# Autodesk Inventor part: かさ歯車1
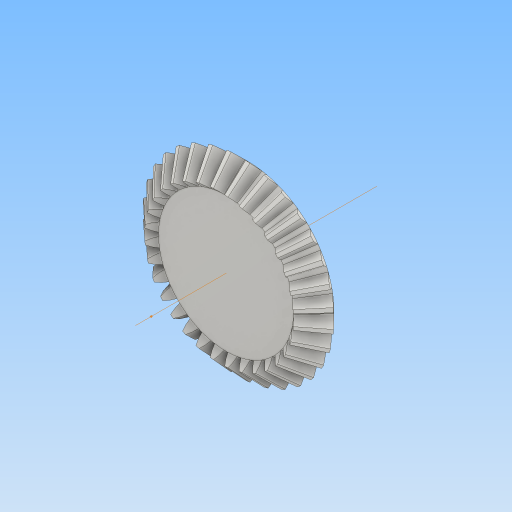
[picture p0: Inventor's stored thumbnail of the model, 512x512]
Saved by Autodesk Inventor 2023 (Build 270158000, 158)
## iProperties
Created: 2024-05
Part Number: かさ歯車1
Material: Steel, Mild
Document SubType Name: Modeling
Designer: kumagai
Categories: <?xml version="1.0" encoding="UTF-16"?> <MemberInstance><Categories><FamilyTemplate><FamilyTemplateParameter ValueType="xs:double" Id="1" ObjectReferenceKey="da
Mass: 60.9118 g
Surface Area: 34.3074 cm^2
Volume: 7.7496 cm^3
Density: 7.86 g/cm^3
Appearance: Steel
CustomPartVersion: 1
Author: kumagai
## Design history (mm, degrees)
node "上側の点"
node "メッシュ平面2"
sketch "歯のボディ スケッチ"
  geometry: L1 (0, 0)-(15.151, -16.849); L2 (15.151, -16.849)-(16.707, -15.293); L3 (16.707, -15.293)-(0, 0); L4 (16, -16)-(0, 0); L5 (11.803, -13.125)-(13.015, -11.914); L6 (15.151, -16.849)-(11.803, -13.125); L7 (16.707, -15.293)-(13.015, -11.914); L8 (0, -39.387)-(0, 6.564) reference; L9 (0, -16)-(16.707, -16)
  constraints: 16 end point, 4 point on line, 3 perpendicular, 2 collinear, 1 horizontal alignment, 1 vertical alignment
  dimensions: "d0" = 32 diameter of L4.start L8 (= da_de); "d1" = 30.30294 diameter of L1.end L8 (= da_dfe); "d2" = 33.41421 diameter of L2.end L8 (= da_dae); "d3" = 5 distance between parallel lines of L2 L5 (= da_b); "d4" = 15.29289 vertical distance of L2.end L1.start (= da_ve)
revolve "歯のボディ" sketch "歯のボディ スケッチ" stored, may be unused: angle "d5" = 90 deg
node "始点"
node "歯の平面"
sketch "開始スケッチ"
  geometry: L1 (0, -23.505)-(0, 10.645) reference; L2 (-0.366, -1.464)-(0.366, -1.464); A1 r 8.083 centre (-8.298, -3.019) between (-0.366, -1.464) and (-1.666, 1.603); A2 r 8.083 centre (8.298, -3.019) between (1.666, 1.603) and (0.366, -1.464); A3 r 24.287 centre (0, -22.627) between (1.666, 1.603) and (-1.666, 1.603); 1 further point
  constraints: 6 point on circle, 3 centre point, 3 symmetric about line, 2 end point, 1 coincident, 1 perpendicular, 1 other
  dimensions: "d7" = 8.08317 radius of A1 (= fd_rr); "d8" = 8.29774 horizontal distance of point (0, -22.627) A1.centre (= fd_x); "d9" = 19.60833 vertical distance of point (0, -22.627) A1.centre (= fd_y); "d57" = 24.28742 radius of A3 (= 0.5 x fd_dva + 0.3 x da_he); "d58" = 21.16342 distance from line of A3.centre L2 (= 0.5 x fd_dva - 1.12 x da_he)
node "終了側の点"
  node "終了平面"
sketch "終了側スケッチ"
  geometry: L1 (0, -15.354)-(0, 6.953) reference; L2 (-0.283, -1.133)-(0.283, -1.133); A1 r 6.258 centre (-6.424, -2.337) between (-0.283, -1.133) and (-1.29, 1.241); A2 r 6.258 centre (6.424, -2.337) between (1.29, 1.241) and (0.283, -1.133); A3 r 18.803 centre (0, -17.517) between (1.29, 1.241) and (-1.29, 1.241); 1 further point
  constraints: 6 point on circle, 3 centre point, 3 symmetric about line, 2 end point, 1 coincident, 1 other
  dimensions: "d12" = 6.25773 radius of A1 (computed from fd_rr, fd_ratio); "d15" = 6.42384 horizontal distance of A1.centre point (0, -17.517) (computed from fd_x, fd_ratio); "d16" = 15.18014 vertical distance of A1.centre point (0, -17.517) (computed from fd_y, fd_ratio); "d59" = 18.80254 radius of A3 (computed from d57, fd_ratio); "d60" = 16.38404 distance from line of A3.centre L2 (computed from d58, fd_ratio)
feature "Loft" sketch "終了側スケッチ" dims "d17" = 0, "d18" = 90 deg, "d19" = 0, "d20" = 90 deg, "d89" = 0, "da_teethtype" = 0 [user parameter]
sketch "3D スケッチ(右)"
  node "Helical Curve Right" dims "d65" = 173.72889 (computed from da_dm, da_delta, da_beta), "d66" = 31.5, "d67" = 32 (= da_de), "d68" = -45 deg (= -da_delta), "d69" = 3.61332 (computed from fd_loft, da_delta)
node "終了平面(右)"
sketch "終了側スケッチ(右)"
  geometry: L1 (0, -23.46)-(0, 9.709) reference; L2 (-0.283, -1.133)-(0.283, -1.133); A1 r 6.258 centre (-6.424, -2.337) between (-0.283, -1.133) and (-1.29, 1.241); A2 r 6.258 centre (6.424, -2.337) between (1.29, 1.241) and (0.283, -1.133); A3 r 18.803 centre (0, -17.517) between (1.29, 1.241) and (-1.29, 1.241); 1 further point
  constraints: 6 point on circle, 3 centre point, 3 symmetric about line, 2 end point, 1 coincident, 1 perpendicular, 1 other
  dimensions: "d70" = 6.42384 horizontal distance of A3.centre A1.centre (computed from fd_x, fd_ratio); "d71" = 15.18014 vertical distance of point (0, -17.517) A1.centre (computed from fd_y, fd_ratio); "d72" = 6.25773 radius of A1 (computed from fd_rr, fd_ratio); "d73" = 16.38404 distance from line of point (0, -17.517) L2 (computed from d58, fd_ratio); "d74" = 18.80254 radius of A3 (computed from d57, fd_ratio)
feature "ロフト(右)" sketch "終了側スケッチ(右)" dims "d75" = 0, "d77" = 0, "d79" = 0, "d80" = 90 deg, "d85" = 20, "d92" = 90 deg, "d93" = 90 deg, "da_teethtype" = 0 [user parameter]
sketch "3D スケッチ(左)"
  node "Helical Curve Left" dims "d26" = 173.72889 (computed from da_dm, da_delta, da_beta), "d27" = 3.61332 (computed from fd_loft, da_delta), "d28" = 32 (= da_de), "d29" = -45 deg (= -da_delta)
node "終了平面(左)"
sketch "終了側スケッチ(左)" dims "d56" = 9.20604 (derived)
  geometry: L1 (0, -29.116)-(0, 12.094) reference; L2 (-0.283, -1.128)-(0.283, -1.128); A1 r 6.258 centre (-6.424, -2.332) between (-0.283, -1.128) and (-1.29, 1.246); A2 r 6.258 centre (6.424, -2.332) between (1.29, 1.246) and (0.283, -1.128); A3 r 18.803 centre (0, -17.512) between (1.29, 1.246) and (-1.29, 1.246); 2 further points; 1 other entity
  constraints: 6 point on circle, 3 centre point, 3 symmetric about line, 2 end point, 1 coincident, 2 other
  dimensions: "d30" = 6.25773 radius of A1 (computed from fd_rr, fd_ratio); "d31" = 6.42384 horizontal distance of point (0, -17.512) A1.centre (computed from fd_x, fd_ratio); "d32" = 15.18014 vertical distance of A1.centre point (0, -17.512) (computed from fd_y, fd_ratio); "d61" = 18.80254 radius of A3 (computed from d57, fd_ratio); "d62" = 16.38404 distance from line of point (0, -17.512) L2 (computed from d58, fd_ratio)
feature "ロフト(左)" sketch "終了側スケッチ(左)" dims "d35" = 0, "d37" = 0, "d39" = 0, "d40" = 90 deg, "d84" = 10, "d90" = 90 deg, "d91" = 90 deg, "da_teethtype" = 0 [user parameter]
sketch "ボディ スケッチ"
  geometry: L1 (0, -35.038)-(0, -19.531) reference; L2 (15.151, -16.849)-(11.803, -13.125) reference; L3 (11.803, -13.125)-(0, -13.125); L4 (15.151, -16.849)-(0, -16.849)
  constraints: 4 end point, 2 perpendicular, 2 point on line
revolve "固定ボディ" sketch "ボディ スケッチ" stored, may be unused: angle "d46" = 90 deg
sketch "Sketch6"
  geometry: L1 (16, -16)-(0, 0) reference; L2 (0, -37.8)-(0, 6.3) reference
feature "ピッチ円直径" sketch "Sketch6" dims angle "d47" = 90 deg
body "Solid1"
pattern_circular "Circular Pattern" dims angle "d22" = 360 deg, "d88" = 0, "da_teethtype" = 0 [user parameter]
pattern_circular "放射状パターン(右)" dims angle "d82" = 360 deg, "da_teethtype" = 0 [user parameter]
pattern_circular "放射状パターン(左)" dims angle "d42" = 360 deg, "da_teethtype" = 0 [user parameter]
body "Srf1"
other parameters: "da_b" = 5 [user parameter; used in 2 equation terms], "da_de" = 32 [user parameter; used in 4 equation terms], "da_dae" = 33.41421 [user parameter; used in 2 equation terms], "da_dfe" = 30.30294 [user parameter; used in 1 equation term], "da_le" = 22.62742 [user parameter; used in 1 equation term], "da_omega" = 90 deg [user parameter; used in 1 equation term], "da_beta" = 0 [user parameter; used in 2 equation terms], "da_delta" = 45 deg [user parameter; used in 8 equation terms], "da_alpha" = 20 deg [user parameter; used in 2 equation terms], "da_he" = 2.2 [user parameter; used in 4 equation terms], "da_ve" = 15.29289 [user parameter; used in 1 equation term], "fd_dv" = 45.25483 (computed from da_de, da_delta) [user parameter; used in 1 equation term], "fd_dva" = 47.25483 (computed from da_dae, da_delta) [user parameter; used in 3 equation terms], "fd_dvb" = 42.52563 (computed from fd_dv, da_alpha) [user parameter; used in 2 equation terms], "da_zv" = 452.54834 [user parameter; used in 1 equation term], "fd_loft" = 5.11 (= da_b + 0.05 x da_he) [user parameter; used in 4 equation terms], "fd_ratio" = 7.74168 (computed from da_le, fd_loft) [user parameter; used in 15 equation terms], "fd_rr" = 8.08317 (computed from fd_dd, fd_dvb) [user parameter; used in 6 equation terms], "fd_angle" = 0.35096 (computed from da_zv) [user parameter; used in 4 equation terms], "fd_x1" = 0.79396 (computed from da_dvw, fd_angle) [user parameter; used in 1 equation term], "fd_y1" = 22.61348 (computed from da_dvw, fd_angle) [user parameter; used in 1 equation term], "fd_x2" = 7.50378 (computed from fd_rr, fd_angle2, fd_angle) [user parameter; used in 1 equation term], "fd_y2" = 3.00515 (computed from fd_rr, fd_angle2, fd_angle) [user parameter; used in 1 equation term], "fd_x" = 8.29774 (= fd_x1 + fd_x2) [user parameter; used in 4 equation terms], "fd_y" = 19.60833 (= fd_y1 - fd_y2) [user parameter; used in 4 equation terms], "fd_angle2" = 3.45829 (computed from fd_dvb, fd_dd, da_alpha) [user parameter; used in 2 equation terms], "fd_dd" = 45.49483 (= fd_dva - 0.8 x da_he) [user parameter; used in 2 equation terms], "da_dvw" = 45.25483 [user parameter; used in 2 equation terms], "d11" = 5.11 (= fd_loft), "da_dm" = 28.46447 [user parameter; used in 2 equation terms], "da_x" = 0 [user parameter], "da_m" = 1 [user parameter], "d48" = 0, "d49" = 0, "d50" = 90 deg (= da_omega), "d51" = 0.98175 (computed from da_z), "d52" = 0, "d53" = 0, "d54" = 0
